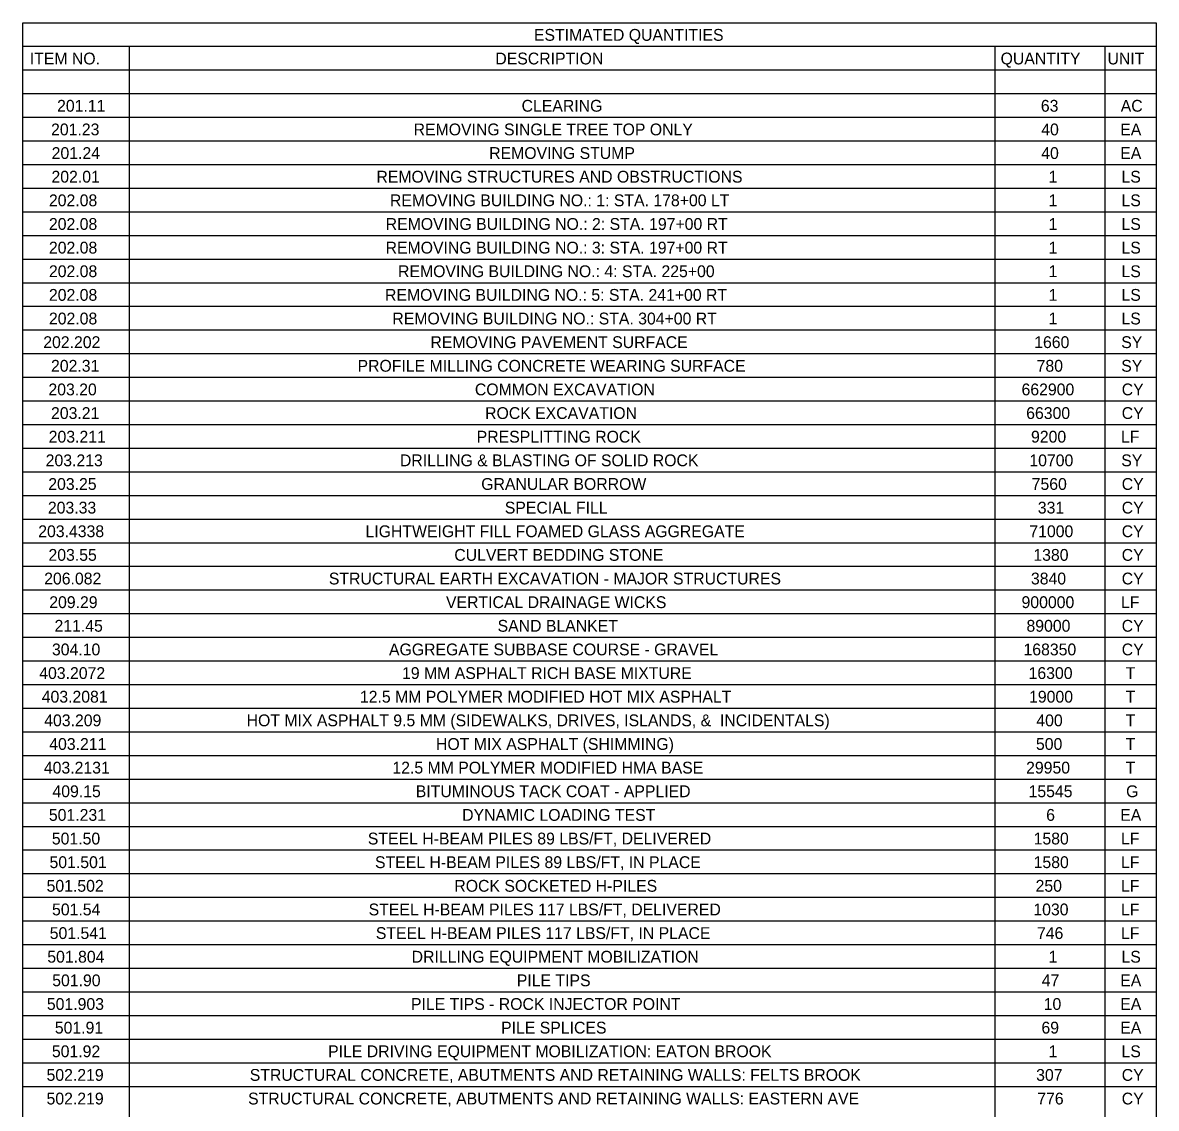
# Model space of a CAD drawing. Extents: x -18.7 to 5.6, y -2.7 to 4.
# Drawn here: x -18.69 to -17.746, y 3.071 to 3.975 of the extents above; entities that cross this region are included whole.
import ezdxf

# ---------------------------------------------------------------- set-up
doc = ezdxf.new("R2010")
doc.units = 0
doc.layers.add('ANNOTATION', color=7, linetype='Continuous')
doc.layers.add('BORDER', color=7, linetype='Continuous')

msp = doc.modelspace()

# ---------------------------------------------------------------- linework, layer by layer
at = {"layer": 'ANNOTATION'}
msp.add_line((-18.69032, 3.91573), (-18.60174, 3.91573), dxfattribs=at)
at = {"layer": 'BORDER'}
for p, q in [((-18.69032, 3.9551), (-17.74604, 3.9551)), ((-18.60174, 3.9551), (-18.60174, 2.24242)), ((-17.88042, 3.9551), (-17.88042, 2.24242)), ((-17.78903, 3.9551), (-17.78903, 2.24242)), ((-18.69032, 3.93542), (-17.74604, 3.93542)), ((-18.69032, 3.91573), (-17.74604, 3.91573)), ((-18.69032, 3.89604), (-17.74604, 3.89604)), ((-18.69032, 3.87636), (-17.74604, 3.87636)), ((-18.69032, 3.85667), (-17.74604, 3.85667)), ((-18.69032, 3.83699), (-17.74604, 3.83699)), ((-18.69032, 3.8173), (-17.74604, 3.8173)), ((-18.69032, 3.79761), (-17.74604, 3.79761)), ((-18.69032, 3.77793), (-17.74604, 3.77793)), ((-18.69032, 3.75824), (-17.74604, 3.75824)), ((-18.69032, 3.73856), (-17.74604, 3.73856)), ((-18.69032, 3.71887), (-17.74604, 3.71887)), ((-18.69032, 3.69918), (-17.74604, 3.69918)), ((-18.69032, 3.6795), (-17.74604, 3.6795)), ((-18.69032, 3.65981), (-17.74604, 3.65981)), ((-18.69032, 3.64013), (-17.74604, 3.64013)), ((-18.69032, 3.62044), (-17.74604, 3.62044)), ((-18.69032, 3.60075), (-17.74604, 3.60075)), ((-18.69032, 3.58107), (-17.74604, 3.58107)), ((-18.69032, 3.56138), (-17.74604, 3.56138)), ((-18.69032, 3.5417), (-17.74604, 3.5417)), ((-18.69032, 3.52201), (-17.74604, 3.52201)), ((-18.69032, 3.50232), (-17.74604, 3.50232)), ((-18.69032, 3.48264), (-17.74604, 3.48264)), ((-18.69032, 3.46295), (-17.74604, 3.46295)), ((-18.69032, 3.44327), (-17.74604, 3.44327)), ((-18.69032, 3.42358), (-17.74604, 3.42358)), ((-18.69032, 3.40389), (-17.74604, 3.40389)), ((-18.69032, 3.38421), (-17.74604, 3.38421)), ((-18.69032, 3.36452), (-17.74604, 3.36452)), ((-18.69032, 3.34484), (-17.74604, 3.34484)), ((-18.69032, 3.32515), (-17.74604, 3.32515)), ((-18.69032, 3.30546), (-17.74604, 3.30546)), ((-18.69032, 3.28578), (-17.74604, 3.28578)), ((-18.69032, 3.26609), (-17.74604, 3.26609)), ((-18.69032, 3.24641), (-17.74604, 3.24641)), ((-18.69032, 3.22672), (-17.74604, 3.22672)), ((-18.69032, 3.20703), (-17.74604, 3.20703)), ((-18.69032, 3.18735), (-17.74604, 3.18735)), ((-18.69032, 3.16766), (-17.74604, 3.16766)), ((-18.69032, 3.14798), (-17.74604, 3.14798)), ((-18.69032, 3.12829), (-17.74604, 3.12829)), ((-18.69032, 3.1086), (-17.74604, 3.1086)), ((-18.69032, 3.08892), (-17.74604, 3.08892))]:
    msp.add_line(p, q, dxfattribs=at)
msp.add_lwpolyline([(-18.69032, 3.97479), (-17.74604, 3.97479), (-17.74604, 2.24242), (-18.69032, 2.24242)], close=True, dxfattribs=at)

# ---------------------------------------------------------------- texts
at = {"layer": 'ANNOTATION'}
for s, height, p in [('201.11', 0.009843, (-18.66167, 3.90064)), ('CLEARING', 0.009843, (-18.27474, 3.90064)), ('63', 0.009843, (-17.84223, 3.90064)), ('AC', 0.009843, (-17.77569, 3.90064)), ('201.23', 0.009843, (-18.66667, 3.88095)), ('REMOVING SINGLE TREE TOP ONLY', 0.009843, (-18.36468, 3.88095)), ('40', 0.009843, (-17.84189, 3.88095)), ('EA', 0.009843, (-17.77611, 3.88095)), ('201.24', 0.009843, (-18.66617, 3.86127)), ('REMOVING STUMP', 0.009843, (-18.30174, 3.86127)), ('40', 0.009843, (-17.84189, 3.86127)), ('EA', 0.009843, (-17.77611, 3.86127)), ('202.01', 0.009843, (-18.66632, 3.84158)), ('REMOVING STRUCTURES AND OBSTRUCTIONS', 0.009843, (-18.39566, 3.84158)), ('1', 0.00984, (-17.83576, 3.84158)), ('LS', 0.009843, (-17.77506, 3.84158)), ('202.08', 0.009843, (-18.66845, 3.8219)), ('REMOVING BUILDING NO.: 1: STA. 178+00 LT', 0.009843, (-18.38439, 3.8219)), ('1', 0.00984, (-17.83576, 3.8219)), ('LS', 0.009843, (-17.77506, 3.8219)), ('202.08', 0.009843, (-18.66845, 3.80221)), ('REMOVING BUILDING NO.: 2: STA. 197+00 RT', 0.009843, (-18.38795, 3.80221)), ('1', 0.00984, (-17.83576, 3.80221)), ('LS', 0.009843, (-17.77506, 3.80221)), ('202.08', 0.009843, (-18.66845, 3.78252)), ('REMOVING BUILDING NO.: 3: STA. 197+00 RT', 0.009843, (-18.38803, 3.78252)), ('1', 0.00984, (-17.83576, 3.78252)), ('LS', 0.009843, (-17.77506, 3.78252)), ('202.08', 0.009843, (-18.66845, 3.76284)), ('REMOVING BUILDING NO.: 4: STA. 225+00', 0.009843, (-18.37765, 3.76284)), ('1', 0.00984, (-17.83576, 3.76284)), ('LS', 0.009843, (-17.77506, 3.76284)), ('202.08', 0.009843, (-18.66845, 3.74315)), ('REMOVING BUILDING NO.: 5: STA. 241+00 RT', 0.009843, (-18.38849, 3.74315)), ('1', 0.00984, (-17.83576, 3.74315)), ('LS', 0.009843, (-17.77506, 3.74315)), ('202.08', 0.009843, (-18.66845, 3.72347)), ('REMOVING BUILDING NO.: STA. 304+00 RT', 0.009843, (-18.3824, 3.72347)), ('1', 0.00984, (-17.83576, 3.72347)), ('LS', 0.009843, (-17.77506, 3.72347)), ('202.202', 0.009843, (-18.67318, 3.70378)), ('REMOVING PAVEMENT SURFACE', 0.009843, (-18.35068, 3.70378)), ('1660', 0.009843, (-17.84777, 3.70378)), ('SY', 0.009843, (-17.77526, 3.70378)), ('202.31', 0.009843, (-18.66671, 3.68409)), ('PROFILE MILLING CONCRETE WEARING SURFACE', 0.009843, (-18.41139, 3.68409)), ('780', 0.009843, (-17.84576, 3.68409)), ('SY', 0.009843, (-17.77526, 3.68409)), ('203.20', 0.009843, (-18.66888, 3.66441)), ('COMMON EXCAVATION', 0.009843, (-18.31364, 3.66441)), ('662900', 0.009843, (-17.85831, 3.66441)), ('CY', 0.009843, (-17.77487, 3.66441)), ('203.21', 0.009843, (-18.66671, 3.64472)), ('ROCK EXCAVATION', 0.009843, (-18.30514, 3.64472)), ('66300', 0.009843, (-17.85444, 3.64472)), ('CY', 0.009843, (-17.77487, 3.64472)), ('203.211', 0.009843, (-18.66865, 3.62504)), ('PRESPLITTING ROCK', 0.009843, (-18.31215, 3.62504)), ('9200', 0.009843, (-17.85041, 3.62504)), ('LF', 0.009843, (-17.77549, 3.62504)), ('203.213', 0.009843, (-18.67116, 3.60535)), ('DRILLING & BLASTING OF SOLID ROCK       ', 0.009843, (-18.3761, 3.60535)), ('10700', 0.009843, (-17.8518, 3.60535)), ('SY', 0.009843, (-17.77526, 3.60535)), ('203.25', 0.009843, (-18.669, 3.58566)), ('GRANULAR BORROW', 0.009843, (-18.30836, 3.58566)), ('7560', 0.009843, (-17.84987, 3.58566)), ('CY', 0.009843, (-17.77487, 3.58566)), ('203.33', 0.009843, (-18.66931, 3.56598)), ('SPECIAL FILL', 0.009843, (-18.28874, 3.56598)), ('331', 0.009843, (-17.84475, 3.56598)), ('CY', 0.009843, (-17.77487, 3.56598)), ('203.4338', 0.009843, (-18.67736, 3.54629)), ('LIGHTWEIGHT FILL FOAMED GLASS AGGREGATE', 0.009843, (-18.40474, 3.54629)), ('71000', 0.009843, (-17.8518, 3.54629)), ('CY', 0.009843, (-17.77487, 3.54629)), ('203.55', 0.009843, (-18.66884, 3.52661)), ('CULVERT BEDDING STONE', 0.009843, (-18.33077, 3.52661)), ('1380', 0.009843, (-17.84847, 3.52661)), ('CY', 0.009843, (-17.77487, 3.52661)), ('206.082', 0.009843, (-18.67241, 3.50692)), ('STRUCTURAL EARTH EXCAVATION - MAJOR STRUCTURES', 0.009843, (-18.43529, 3.50692)), ('3840', 0.009843, (-17.85048, 3.50692)), ('CY', 0.009843, (-17.77487, 3.50692)), ('209.29', 0.009843, (-18.66818, 3.48723)), ('VERTICAL DRAINAGE WICKS', 0.009843, (-18.33772, 3.48723)), ('900000', 0.009843, (-17.85831, 3.48723)), ('LF', 0.009843, (-17.77549, 3.48723)), ('211.45', 0.009843, (-18.6638, 3.46755)), ('SAND BLANKET', 0.009843, (-18.29473, 3.46755)), ('89000', 0.009843, (-17.8542, 3.46755)), ('CY', 0.009843, (-17.77487, 3.46755)), ('304.10', 0.009843, (-18.66593, 3.44786)), ('AGGREGATE SUBBASE COURSE - GRAVEL', 0.009843, (-18.38521, 3.44786)), ('168350', 0.009843, (-17.85668, 3.44786)), ('CY', 0.009843, (-17.77487, 3.44786)), ('403.2072', 0.009843, (-18.67651, 3.42818)), ('19 MM ASPHALT RICH BASE MIXTURE', 0.009843, (-18.37432, 3.42818)), ('16300', 0.009843, (-17.85242, 3.42818)), ('T', 0.00984, (-17.77162, 3.42818)), ('403.2081', 0.009843, (-18.67446, 3.40849)), ('12.5 MM POLYMER MODIFIED HOT MIX ASPHALT', 0.009843, (-18.4094, 3.40849)), ('19000', 0.009843, (-17.85203, 3.40849)), ('T', 0.00984, (-17.77162, 3.40849)), ('403.209', 0.009843, (-18.67237, 3.3888)), ('HOT MIX ASPHALT 9.5 MM (SIDEWALKS, DRIVES, ISLANDS, &  INCIDENTALS)', 0.009843, (-18.50376, 3.3888)), ('400', 0.009843, (-17.84599, 3.3888)), ('T', 0.00984, (-17.77162, 3.3888)), ('403.211', 0.009843, (-18.66818, 3.36912)), ('HOT MIX ASPHALT (SHIMMING)', 0.009843, (-18.34602, 3.36912)), ('500', 0.009843, (-17.8463, 3.36912)), ('T', 0.00984, (-17.77162, 3.36912)), ('403.2131', 0.009843, (-18.67267, 3.34943)), ('12.5 MM POLYMER MODIFIED HMA BASE', 0.009843, (-18.38236, 3.34943)), ('29950', 0.009843, (-17.85451, 3.34943)), ('T', 0.00984, (-17.77162, 3.34943)), ('409.15', 0.009843, (-18.66551, 3.32975)), ('BITUMINOUS TACK COAT - APPLIED', 0.009843, (-18.36289, 3.32975)), ('15545', 0.009843, (-17.85246, 3.32975)), ('G', 0.00984, (-17.77123, 3.32975)), ('501.231', 0.009843, (-18.66849, 3.31006)), ('DYNAMIC LOADING TEST', 0.009843, (-18.32425, 3.31006)), ('6', 0.00984, (-17.83778, 3.31006)), ('EA', 0.009843, (-17.77611, 3.31006)), ('501.50', 0.009843, (-18.66601, 3.29037)), ('STEEL H-BEAM PILES 89 LBS/FT, DELIVERED', 0.009843, (-18.40283, 3.29037)), ('1580', 0.009843, (-17.84824, 3.29037)), ('LF', 0.009843, (-17.77549, 3.29037)), ('501.501', 0.009843, (-18.66795, 3.27069)), ('STEEL H-BEAM PILES 89 LBS/FT, IN PLACE', 0.009843, (-18.39684, 3.27069)), ('1580', 0.009843, (-17.84824, 3.27069)), ('LF', 0.009843, (-17.77549, 3.27069)), ('501.502', 0.009843, (-18.67039, 3.251)), ('ROCK SOCKETED H-PILES', 0.009843, (-18.33076, 3.251)), ('250', 0.009843, (-17.84661, 3.251)), ('LF', 0.009843, (-17.77549, 3.251)), ('501.54', 0.009843, (-18.66586, 3.23132)), ('STEEL H-BEAM PILES 117 LBS/FT, DELIVERED', 0.009843, (-18.40213, 3.23132)), ('1030', 0.009843, (-17.84847, 3.23132)), ('LF', 0.009843, (-17.77549, 3.23132)), ('501.541', 0.009843, (-18.66779, 3.21163)), ('STEEL H-BEAM PILES 117 LBS/FT, IN PLACE', 0.009843, (-18.39614, 3.21163)), ('746', 0.009843, (-17.84545, 3.21163)), ('LF', 0.009843, (-17.77549, 3.21163)), ('501.804', 0.009843, (-18.66981, 3.19194)), ('DRILLING EQUIPMENT MOBILIZATION', 0.009843, (-18.3663, 3.19194)), ('1', 0.00984, (-17.83576, 3.19194)), ('LS', 0.009843, (-17.77506, 3.19194)), ('501.90', 0.009843, (-18.6657, 3.17226)), ('PILE TIPS', 0.009843, (-18.27873, 3.17226)), ('47', 0.009843, (-17.8415, 3.17226)), ('EA', 0.009843, (-17.77611, 3.17226)), ('501.903', 0.009843, (-18.67016, 3.15257)), ('PILE TIPS - ROCK INJECTOR POINT', 0.009843, (-18.36689, 3.15257)), ('10', 0.009843, (-17.83987, 3.15257)), ('EA', 0.009843, (-17.77611, 3.15257)), ('501.91', 0.009843, (-18.66353, 3.13289)), ('PILE SPLICES', 0.009843, (-18.29183, 3.13289)), ('69', 0.009843, (-17.84173, 3.13289)), ('EA', 0.009843, (-17.77611, 3.13289)), ('501.92', 0.009843, (-18.66597, 3.1132)), ('PILE DRIVING EQUIPMENT MOBILIZATION: EATON BROOK', 0.009843, (-18.43588, 3.1132)), ('1', 0.00984, (-17.83576, 3.1132)), ('LS', 0.009843, (-17.77506, 3.1132)), ('502.219', 0.009843, (-18.67043, 3.09351)), ('STRUCTURAL CONCRETE, ABUTMENTS AND RETAINING WALLS: FELTS BROOK', 0.009843, (-18.50118, 3.09351)), ('307', 0.009843, (-17.84615, 3.09351)), ('CY', 0.009843, (-17.77487, 3.09351)), ('502.219', 0.009843, (-18.67043, 3.07383)), ('STRUCTURAL CONCRETE, ABUTMENTS AND RETAINING WALLS: EASTERN AVE', 0.009843, (-18.50259, 3.07383)), ('776', 0.009843, (-17.84522, 3.07383)), ('CY', 0.009843, (-17.77487, 3.07383))]:
    msp.add_text(s, height=height, dxfattribs=at).set_placement(p)
at = {"layer": 'BORDER'}
for s, height, p in [('ESTIMATED QUANTITIES', 0.0098425, (-18.26447, 3.9597)), ('ITEM NO.', 0.009843, (-18.68441, 3.94001)), ('DESCRIPTION', 0.0098425, (-18.29662, 3.94001)), ('QUANTITY', 0.009843, (-17.87574, 3.94001)), ('UNIT', 0.009843, (-17.78672, 3.94001))]:
    msp.add_text(s, height=height, dxfattribs=at).set_placement(p)

doc.saveas('drawing.dxf')
